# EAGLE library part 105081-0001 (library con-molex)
RIGHT ANGLE MINI-DISPLAYPORT RECEPTACLE Source: http://www.molex.com/pdm_docs/sd/1050810001_sd.pdf
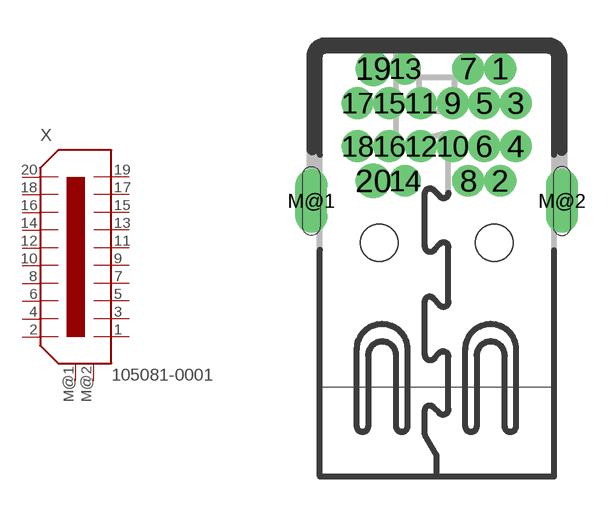
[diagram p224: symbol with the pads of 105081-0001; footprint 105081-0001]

Designator prefix X

## 105081-0001 (MPN: 105081-0001; OC_FARNELL: 1774561; OC_NEWARK: 04R6635)  [105081-0001]
1  1  pas
2  2  pas
3  3  pas
4  4  pas
5  5  pas
6  6  pas
7  7  pas
8  8  pas
9  9  pas
10  10  pas
11  11  pas
12  12  pas
13  13  pas
14  14  pas
15  15  pas
16  16  pas
17  17  pas
18  18  pas
19  19  pas
20  20  pas
M@1  M  in
M@2  M  in

## Footprint 105081-0001 (pad centres in mm)
RIGHT ANGLE MINI-DISPLAYPORT RECEPTACLE Source: http://www.molex.com/pdm_docs/sd/1050810001_sd.pdf
drill 0.6 pad 0.9 round: 1 2.2,11.05; 2 2.2,7.15; 3 2.75,9.85; 4 2.75,8.35; 5 1.65,9.85; 6 1.65,8.35; 7 1.1,11.05; 8 1.1,7.15; 9 0.55,9.85; 10 0.55,8.35; 11 -0.55,9.85; 12 -0.55,8.35; 13 -1.1,11.05; 14 -1.1,7.15; 15 -1.65,9.85; 16 -1.65,8.35; 17 -2.75,9.85; 18 -2.75,8.35
drill 0.7 pad 1 round: 19 -2.2,11.05; 20 -2.2,7.15
drill 0.6 pad 0.9 long: M@1 -4.35,6.45; M@2 4.35,6.45
hole 1.3 at -2,5
hole 1.3 at 2,5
